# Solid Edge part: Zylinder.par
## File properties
Username: bmolnar
Dokumentum tartalom típus: 0
Author: bmolnar
Template: iso metric part.par
Last saved by: bmolnar
Revision: 12
Application: Solid Edge
Sűrűség: 0,000 kg/m^3
Pontosság: 0,990
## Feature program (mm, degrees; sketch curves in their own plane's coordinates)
base feature "unnamed BaseFeature 1"
sketch for "Furat_1" plane through (-0.0005, -4.5, -623) normal (0, 0, -1) x-axis (-1, 0, 0)
  hole centre (-18.0005, 20) bore radius 2.4585
hole "Furat_1" nominal diameter 6 finite  VBottomAngle = 118 deg; ThreadDepth = 15 mm
sketch for "unnamed Hole 1" plane through (-0.0005, -4.5, -623) normal (0, 0, -1) x-axis (-1, 0, 0)
  hole centre (17.9995, 20) bore radius 2.4585
hole "unnamed Hole 1" finite
sketch for "unnamed Hole 2" plane through (-0.0005, -4.5, -623) normal (0, 0, -1) x-axis (-1, 0, 0)
  hole centre (17.9995, -20) bore radius 2.4585
hole "unnamed Hole 2" finite
sketch for "unnamed Hole 3" plane through (-0.0005, -4.5, -623) normal (0, 0, -1) x-axis (-1, 0, 0)
  hole centre (-18.0005, -20) bore radius 2.4585
hole "unnamed Hole 3" finite
sketch for "Furat_5" plane through (0.0005, -4.5, 27) normal (0, 0, 1) x-axis (0, 1, 0)
  hole centre (-20, 18.0005) bore radius 2.4585
hole "Furat_5" nominal diameter 6 finite  VBottomAngle = 118 deg; ThreadDepth = 15 mm
sketch for "unnamed Hole 4" plane through (0.0005, -4.5, 27) normal (0, 0, 1) x-axis (0, 1, 0)
  hole centre (20, 18.0005) bore radius 2.4585
hole "unnamed Hole 4" finite
sketch for "unnamed Hole 5" plane through (0.0005, -4.5, 27) normal (0, 0, 1) x-axis (0, 1, 0)
  hole centre (20, -17.9995) bore radius 2.4585
hole "unnamed Hole 5" finite
sketch for "unnamed Hole 6" plane through (0.0005, -4.5, 27) normal (0, 0, 1) x-axis (0, 1, 0)
  hole centre (-20, -17.9995) bore radius 2.4585
hole "unnamed Hole 6" finite
sketch for "Furat_9" plane through (0, -31.7, 16) normal (0, -1, 0) x-axis (0, 0, -1)
hole "Furat_9" diameter 13.157 finite  ThreadDepth = 10 mm
sketch for "unnamed Hole 7" plane through (0, -31.7, 16) normal (0, -1, 0) x-axis (0, 0, -1)
hole "unnamed Hole 7" finite
sketch for "Furat_11" plane through (25.2, -2.5, 16.5) normal (1, 0, 0) x-axis (0, 0, -1)
hole "Furat_11" diameter 13.157 finite  ThreadDepth = 10 mm
sketch for "unnamed Hole 8" plane through (25.2, -2.5, 16.5) normal (1, 0, 0) x-axis (0, 0, -1)
hole "unnamed Hole 8" finite
sketch for "Furat_13" plane through (0, -2.5, 26.2) normal (0, 0, 1) x-axis (0, -1, 0)
hole "Furat_13" diameter 13.157 finite  ThreadDepth = 10 mm
sketch for "Furat_14" plane through (0, -2.5, -622.2) normal (0, 0, -1) x-axis (0, 1, 0)
hole "Furat_14" diameter 13.157 finite  ThreadDepth = 10 mm
pattern "unnamed Pattern 1" of "Furat_1", "unnamed Hole 1", "unnamed Hole 2", "unnamed Hole 3"
pattern "unnamed Pattern 2" of "Furat_5", "unnamed Hole 4", "unnamed Hole 5", "unnamed Hole 6"
pattern "unnamed Pattern 3" of "Furat_9", "unnamed Hole 7"
pattern "unnamed Pattern 4" of "Furat_11", "unnamed Hole 8"
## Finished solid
Body 1: solid body, 619 faces, 1304 edges, 706 vertices, 16 internal voids.
  Faces by surface: plane 394, cylinder 165, cone 60
  Edges by curve: line 892, circle 394, curve on surface 10, intersection 8
Bounding box of the edges (mm): 52.000 x 56.700 x 650.000, from (-26, -32.5, -623.0002) to (26, 24.2, 27.0002).
Cylindrical faces by radius (mm): R0.15 x16, R0.2 x12, R0.5 x12, R0.7 x12, R1.437 x4, R1.55 x4, R1.75 x4, R1.8727 x2, R2 x10, R2.4585 x16, R2.5 x4, R3 x12, R3.5 x8, R4 x2, R4.2 x8, R4.45 x8, R5.7225 x6, R6 x8, R6.3 x8, R10 x6, R15.9 x2, R16.05 x1
Conical faces (half-angle, radius in mm at the cone's reference point): 45 deg R1.3727 x2, 45 deg R1.437 x4, 45 deg R1.5 x6, 45 deg R1.75 x2, 45 deg R1.8727 x2, 45 deg R2 x6, 45 deg R3 x4, 45 deg R3.3 x2, 45 deg R4 x4, 45 deg R6 x8, 59 deg R2.4585 x8, 59 deg R2.5941 x8, 60 deg R1 x4
Planar faces by outward normal: +x 28, +y 39, +z 50, -x 22, -y 27, -z 50, oblique 178
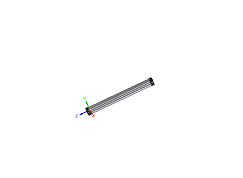
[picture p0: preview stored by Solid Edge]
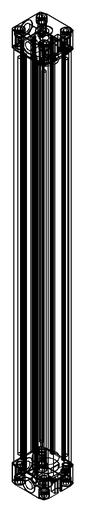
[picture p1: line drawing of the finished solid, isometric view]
